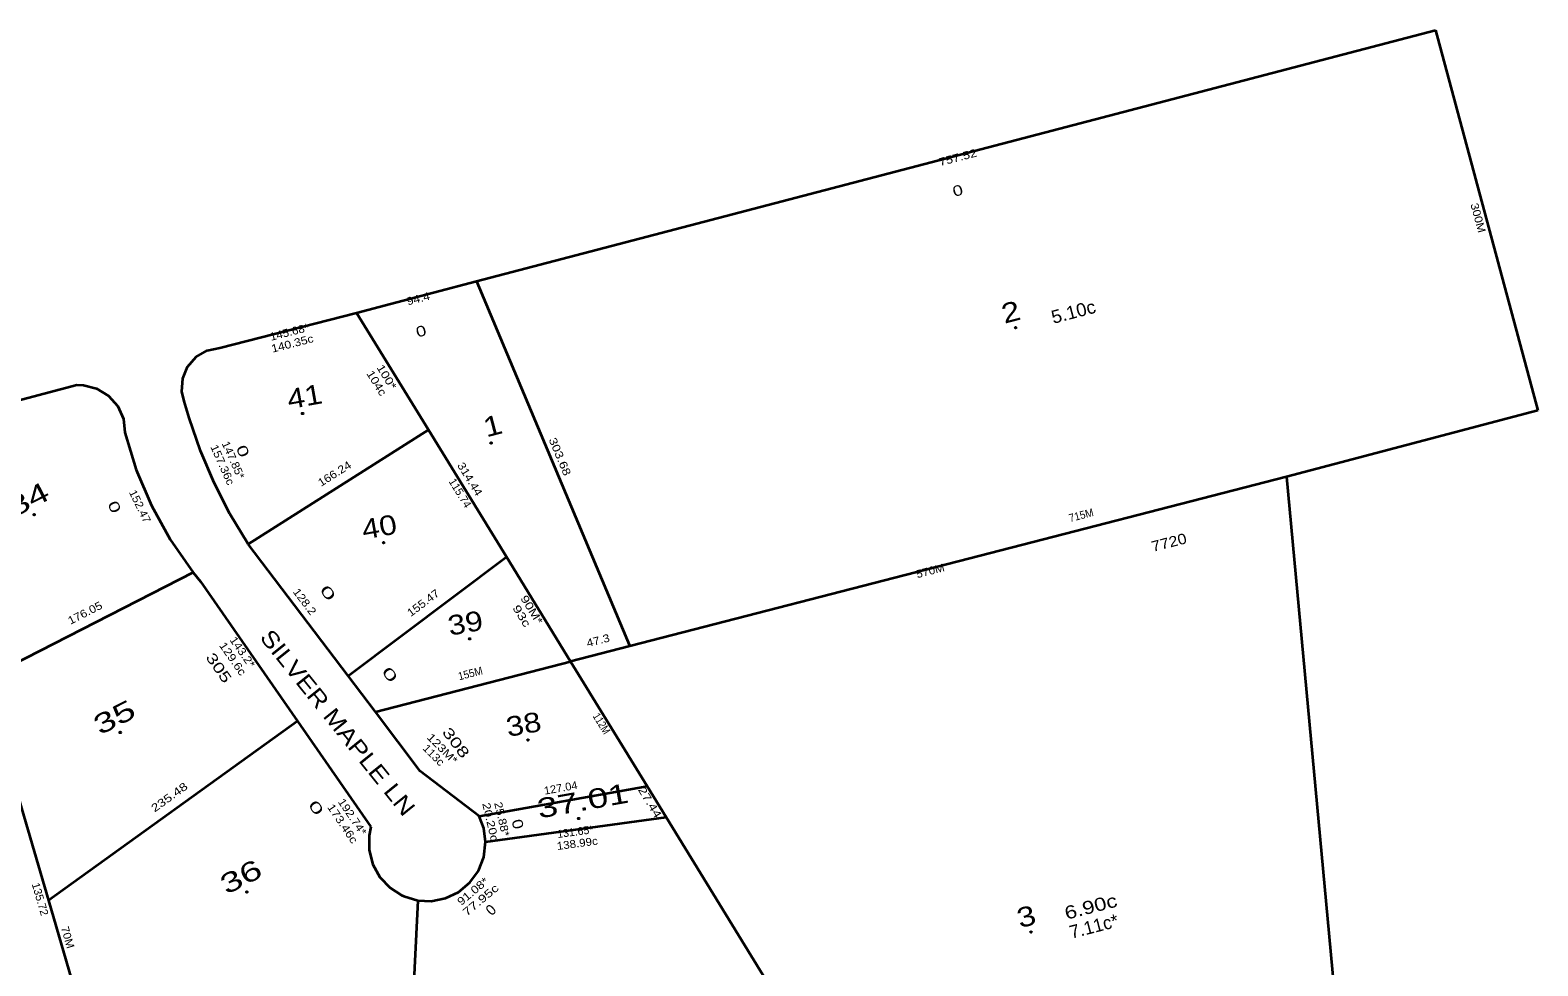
# Model space of a CAD drawing. Extents: x 2546959 to 2550387, y 581906 to 585027.
# Drawn here: x 2549237 to 2550387, y 583531 to 584245 of the extents above; entities that cross this region are included whole.
import ezdxf
from ezdxf.enums import TextEntityAlignment as Align

# ---------------------------------------------------------------- set-up
doc = ezdxf.new("R2010")
doc.units = 0
doc.header["$LTSCALE"] = 2.4
doc.header["$PDMODE"] = 32
doc.header["$PDSIZE"] = 1.2
for name, color, linetype in [('20', 7, 'Continuous'), ('38', 7, 'Continuous'), ('39', 7, 'Continuous'), ('41', 7, 'Continuous'), ('42', 7, 'Continuous')]:
    doc.layers.add(name, color=color, linetype=linetype)
doc.layers.add('40', color=7, linetype='Continuous', lineweight=35)

msp = doc.modelspace()

# ---------------------------------------------------------------- linework, layer by layer
at = {"layer": '40'}
for p, q in [((2549577.233, 584052.931), (2550308.685, 584244.591)), ((2550308.685, 584244.591), (2550386.687, 583954.249)), ((2549511.602, 584035.734), (2549577.233, 584052.931)), ((2549577.233, 584052.931), (2549694.232, 583774.501)), ((2549381.489, 584002.094), (2549485.616, 584029.016)), ((2549485.616, 584029.016), (2549511.602, 584035.734)), ((2549485.616, 584029.016), (2549540.456, 583939.635)), ((2549145.332, 583940.621), (2549272.401, 583973.833)), ((2550386.687, 583954.249), (2550195.063, 583903.767)), ((2549403.085, 583852.376), (2549540.456, 583939.635)), ((2549540.456, 583939.635), (2549599.959, 583842.655)), ((2550195.063, 583903.767), (2549694.232, 583774.501)), ((2550195.063, 583903.767), (2550273.96, 583052.222)), ((2549403.085, 583852.376), (2549402.778, 583852.78)), ((2549479.195, 583751.994), (2549403.085, 583852.376)), ((2549599.959, 583842.655), (2549648.946, 583762.813)), ((2549500.117, 583724.4), (2549648.946, 583762.813)), ((2549534.32, 583679.29), (2549500.117, 583724.4)), ((2549440.609, 583717.371), (2549250.655, 583580.386)), ((2549440.609, 583717.371), (2549496.715, 583636.646)), ((2549579.228, 583644.823), (2549534.32, 583679.29)), ((2549707.304, 583667.698), (2549721.867, 583643.963)), ((2549584.12, 583625.389), (2549721.867, 583643.963)), ((2549721.867, 583643.963), (2549908.935, 583339.07)), ((2549250.655, 583580.386), (2549270.052, 583514.047)), ((2549532.517, 583580.537), (2549525.145, 583432.101))]:
    msp.add_line(p, q, dxfattribs=at)
for points in [[(2549354.267, 583961.416), (2549352.521, 583968.881), (2549353.127, 583978.703), (2549356.862, 583987.805), (2549363.331, 583995.22), (2549371.841, 584000.159), (2549381.489, 584002.094)], [(2549272.401, 583973.833), (2549277.401, 583973.703), (2549287.448, 583971.196), (2549296.532, 583965.692), (2549303.552, 583957.723), (2549307.868, 583948.018), (2549309.082, 583937.467)], [(2549402.778, 583852.78), (2549389.066, 583875.507), (2549376.982, 583899.141), (2549366.585, 583923.565), (2549357.929, 583948.657), (2549354.267, 583961.416)], [(2549309.082, 583937.467), (2549317.723, 583909.123), (2549329.25, 583881.825), (2549343.541, 583855.866), (2549361.129, 583830.668)], [(2549500.117, 583724.4), (2549479.195, 583751.994), (2549599.959, 583842.655)], [(2549361.129, 583830.668), (2549201.357, 583749), (2549231.828, 583644.78), (2549250.655, 583580.386)], [(2549361.129, 583830.668), (2549366.624, 583823.818), (2549440.609, 583717.371)], [(2549694.232, 583774.501), (2549648.946, 583762.813), (2549707.304, 583667.698)], [(2549584.12, 583625.389), (2549582.69, 583635.787), (2549579.228, 583644.823), (2549707.304, 583667.698)], [(2549496.715, 583636.646), (2549495.378, 583630.061), (2549495.388, 583618.881), (2549498.182, 583608.055), (2549503.582, 583598.266), (2549511.25, 583590.13), (2549520.061, 583584.478)], [(2549532.517, 583580.537), (2549542.502, 583580.054), (2549553.477, 583582.18), (2549563.579, 583586.97), (2549572.17, 583594.125), (2549578.709, 583603.194), (2549582.784, 583613.604), (2549584.12, 583625.389)], [(2549520.061, 583584.478), (2549521.728, 583583.784), (2549532.517, 583580.537)]]:
    msp.add_lwpolyline(points, dxfattribs=at)
at = {"layer": '41'}
for p in [(2549988.343, 584017.587), (2549444.511, 583952.085), (2549588.333, 583929.648), (2549239.781, 583874.828), (2549506.316, 583853.583), (2549571.984, 583780.189), (2549305.449, 583708.726), (2549616.406, 583702.932), (2549655.034, 583643.058), (2549402.019, 583587.047), (2550000.138, 583556.447)]:
    msp.add_point(p, dxfattribs=at)

# ---------------------------------------------------------------- texts
at = {"layer": '20', "width": 1.2}
msp.add_text('SILVER MAPLE LN', height=12.5, rotation=308.787, dxfattribs=at).set_placement((2549466.461, 583712.299), align=Align.CENTER)
at = {"layer": '38'}
for s, rotation, width, p in [('2', 14.683, 1.25, (2549986.595, 584022.288)), ('41', 10.127, 1.2, (2549447.399, 583957.683)), ('1', 14.683, 1.25, (2549591.4, 583935.546)), ('34', 27.074, 1.45, (2549238.674, 583879.825)), ('40', 10.127, 1.2, (2549504.328, 583858.251)), ('39', 10.127, 1.2, (2549569.98, 583784.865)), ('35', 27.074, 1.45, (2549304.38, 583713.747)), ('38', 10.127, 1.2, (2549614.406, 583707.64)), ('37.01', 10.127, 1.4, (2549659.554, 583649.209)), ('36', 27.074, 1.45, (2549400.912, 583592.041)), ('3', 14.683, 1.25, (2549998.38, 583561.066))]:
    msp.add_text(s, height=15, rotation=rotation, dxfattribs=dict(at, width=width)).set_placement(p, align=Align.CENTER)
at = {"layer": '39'}
for s, rotation, width, p in [('0', 14.683, 1.3, (2549945.247, 584118.336)), ('0', 14.683, 1.3, (2549535.92, 584011.03)), ('0', 292.053, 1.5, (2549395.267, 583921.902)), ('0', 292.895, 1.5, (2549297.375, 583879.255)), ('7720', 14.472, 1.15, (2550106.335, 583849.848)), ('0', 307.17, 1.95, (2549460.645, 583812.788)), ('305', 304.801, 1.4, (2549377.37, 583755.776)), ('0', 307.169, 1.95, (2549507.897, 583750.496)), ('308', 307.17, 1.45, (2549558.353, 583698.554)), ('0', 304.801, 1.85, (2549451.554, 583649.004)), ('0', 283.215, 1.25, (2549604.771, 583637.874))]:
    msp.add_text(s, height=8, rotation=rotation, dxfattribs=dict(at, width=width)).set_placement(p, align=Align.CENTER)
msp.add_text('0', height=8, rotation=42.681, dxfattribs=at).set_placement((2549590.857, 583570.423), align=Align.CENTER)
at = {"layer": '42'}
for s, rotation, width, p in [('757.52', 14.683, 1.2, (2549945.065, 584144.555)), ('300M', 285.038, 1.15, (2550338.238, 584100.581)), ('94.4', 14.63, 1.15, (2549533.492, 584036.819)), ('145.68*', 14.497, 1.1, (2549435.247, 584011.332)), ('140.35c', 14.497, 1.15, (2549437.487, 584002.587)), ('104c', 301.531, 1.2, (2549498.448, 583973.738)), ('100*', 301.531, 1.25, (2549506.127, 583978.431)), ('157.36c', 294.063, 1.15, (2549380.725, 583911.77)), ('147.85*', 294.063, 1.1, (2549388.938, 583915.396)), ('303.68', 292.793, 1.25, (2549638.071, 583918.054)), ('166.24', 32.424, 1.15, (2549470.502, 583903.625)), ('314.44', 301.531, 1.15, (2549569.651, 583900.495)), ('152.47', 295.982, 1.1, (2549317.832, 583879.932)), ('715M', 14.552, 0.95, (2550039.137, 583871.604)), ('570M', 14.472, 1.1, (2549924.03, 583829.136)), ('128.2', 307.17, 1.15, (2549443.747, 583806.761)), ('155.47', 36.896, 1.15, (2549538.316, 583805.185)), ('90M*', 301.531, 1.3, (2549616.781, 583800.762)), ('176.05', 27.074, 1.15, (2549279.974, 583797.274)), ('93c', 301.531, 1.4, (2549609.101, 583796.068)), ('129.6c', 304.801, 1.2, (2549388.836, 583763.238)), ('143.2*', 304.801, 1.15, (2549396.197, 583768.358)), ('47.3', 14.472, 1.15, (2549670.646, 583776.015)), ('155M', 14.472, 0.95, (2549573.215, 583750.854)), ('112M', 301.531, 0.85, (2549670.038, 583713.94)), ('123M*', 314.832, 1.25, (2549549.072, 583694.251)), ('113c', 314.832, 1.1, (2549542.405, 583689.38)), ('235.48', 35.797, 1.3, (2549344.661, 583656.92)), ('127.04', 10.127, 1.05, (2549641.937, 583663.483)), ('27.44', 301.531, 1.3, (2549706.912, 583653.883)), ('173.46c', 303.888, 1.2, (2549472.582, 583637.524)), ('192.74*', 303.888, 1.15, (2549480.049, 583642.644)), ('20.20c', 283.215, 1.25, (2549584.949, 583639.756)), ('25.88*', 283.215, 1.15, (2549593.695, 583641.89)), ('138.99c', 7.679, 1.1, (2549654.427, 583621.093)), ('135.72', 286.298, 1.05, (2549241.507, 583580.713)), ('91.08*', 39.781, 1.2, (2549576.212, 583585.208)), ('77.95c', 39.781, 1.35, (2549582.263, 583578.624)), ('70M', 286.298, 1.1, (2549262.52, 583551.551))]:
    msp.add_text(s, height=5.999, rotation=rotation, dxfattribs=dict(at, width=width)).set_placement(p, align=Align.CENTER)
for s, width, p in [('5.10c', 1.05, (2550017.125, 584020.464)), ('6.90c', 1.25, (2550027.223, 583565.751))]:
    msp.add_text(s, height=10, rotation=14.683, dxfattribs=dict(at, width=width)).set_placement(p)
for s, rotation, p in [('115.74', 301.531, (2549562.146, 583889.832)), ('131.65*', 7.679, (2549652.881, 583630.002))]:
    msp.add_text(s, height=5.999, rotation=rotation, dxfattribs=at).set_placement(p, align=Align.CENTER)
msp.add_text('7.11c*', height=10, rotation=14.683, dxfattribs=at).set_placement((2550031.024, 583551.24))

doc.saveas('drawing.dxf')
